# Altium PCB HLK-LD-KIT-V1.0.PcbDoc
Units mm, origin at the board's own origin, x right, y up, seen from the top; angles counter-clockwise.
Board outline 37.6 x 27.7 mm, 2 copper layers (Top Layer, Bottom Layer); 25 components, 18 nets, 85 pads, 76 vias.
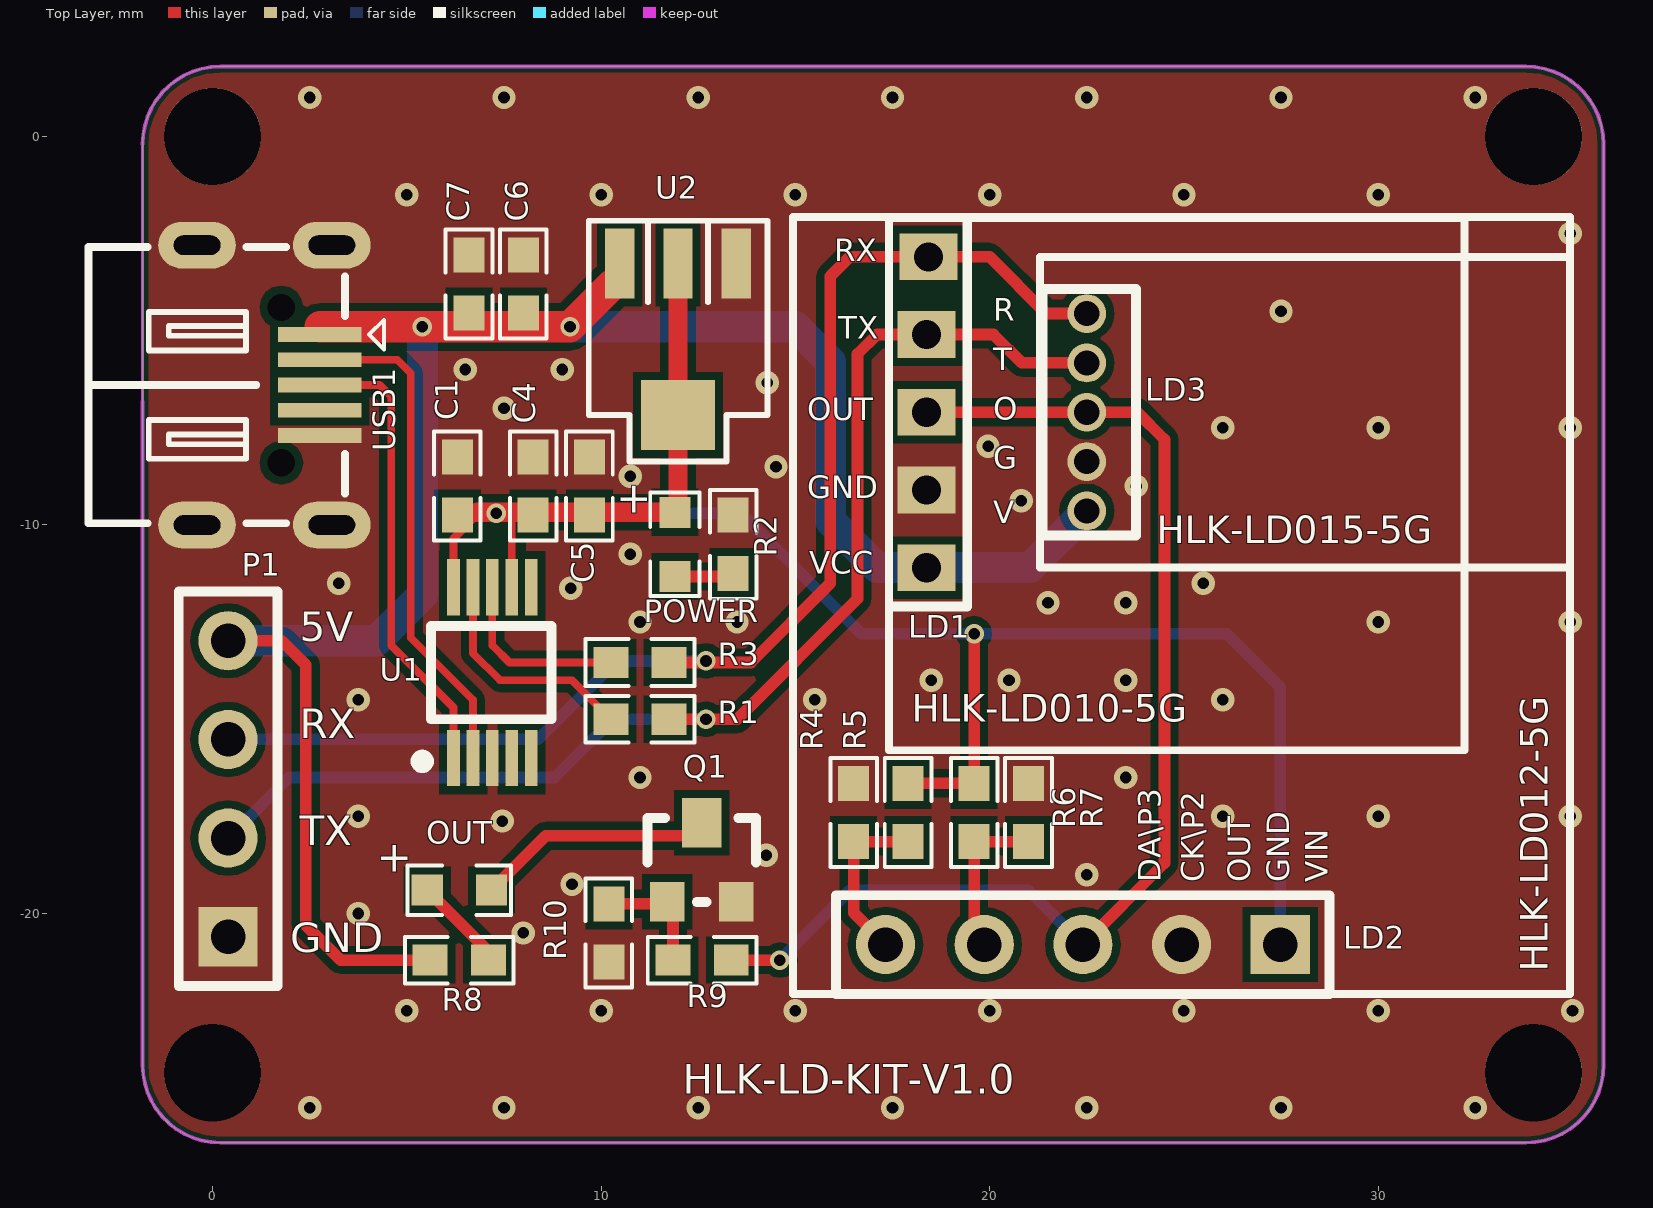
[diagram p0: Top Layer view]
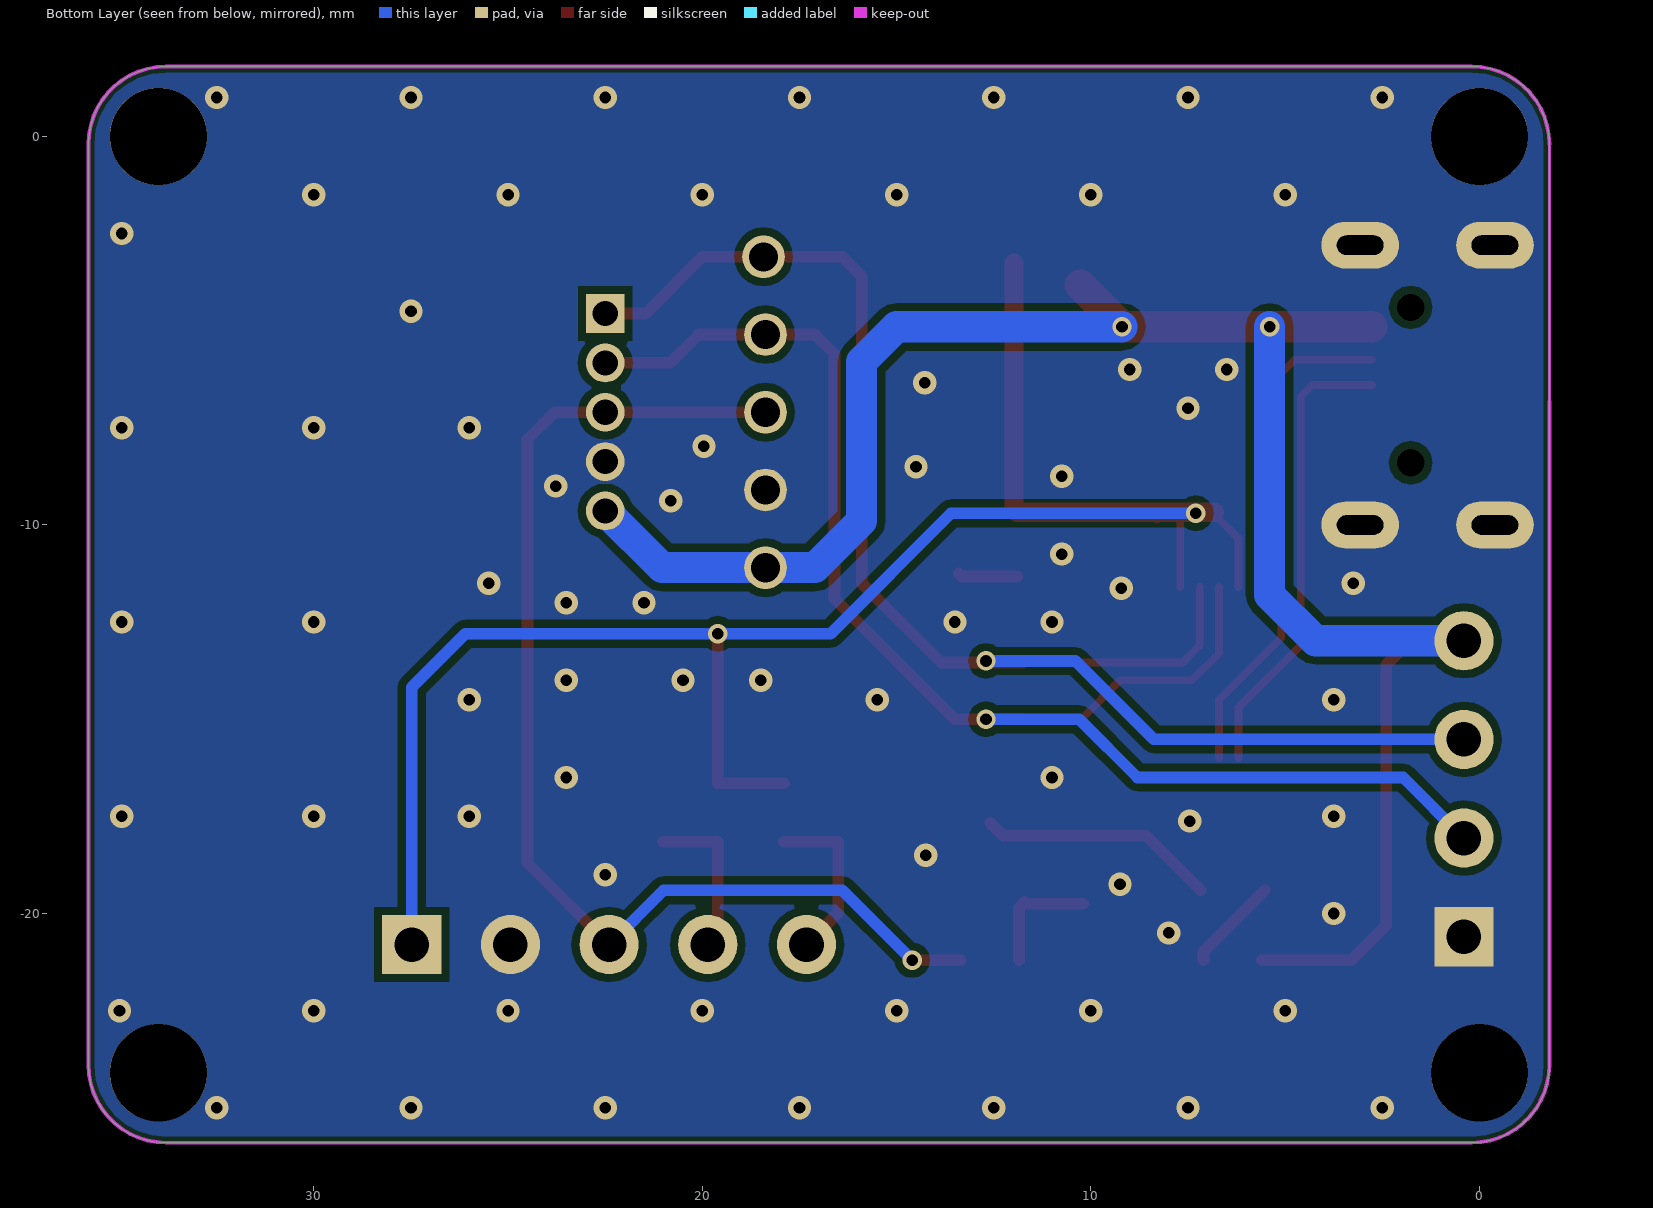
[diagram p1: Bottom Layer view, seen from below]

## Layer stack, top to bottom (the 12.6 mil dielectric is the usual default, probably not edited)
Top Layer: signal copper 0.0356
Dielectric: dielectric 0.32, FR-4, Dk 4.8
Bottom Layer: signal copper 0.0356

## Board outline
-1.8,-23.9 -1.8,-0.2 cw(c0.2,-0.2) 0.2,1.8 33.8,1.8 cw(c33.8,-0.2) 35.8,-0.2 35.8,-23.9 cw(c33.8,-23.9) 33.8,-25.9 0.2,-25.9 cw(c0.2,-23.9)

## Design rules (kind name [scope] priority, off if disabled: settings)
Clearance Clearance_1 [OnLayer('Keep-Out Layer')] p1: gap=0.1
Clearance [All] p2: gap=0.2
PolygonConnect [All] p1: connectstyle=Direct reliefconductorwidth=0.254 reliefentries=4 polygonreliefangle="90 Angle"
RoutingVias [All] p1: holewidth=0.3 width=0.5 viastyle="Through Hole" minholewidth=0.3 minwidth=0.5 maxholewidth=0.711 maxwidth=1.27
SilkscreenOverComponentPads [IsPad] p1: minsilkscreentomaskgap=0.254
SolderMaskExpansion [All] p1: expansion=0.102
TestPointUsage [All] p1: valid=0 allowmultiple=FALSE
Testpoint [(IsPad And (OnTopLayer Or OnBottomLayer))] p1: side=3 testpointundercomponent=TRUE minsize=1.016 maxsize=2.54 preferedsize=1.524 minholesize=0 maxholesize=1.016 preferedholesize=0.813 testpointgrid=0.025 style=297 order=0-112345678
Width 5V [InNet('5V')] p1: maxlimit=2 minlimit=0.3 preferedwidth=0.3
Width [All] p2: maxlimit=2 minlimit=0.2 preferedwidth=0.3
23 further rules are at their usual default settings.

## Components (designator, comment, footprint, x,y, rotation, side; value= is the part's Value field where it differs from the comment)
C1 "0.1uF" 0603 6.3,-9 r270 top
C4 "10uF" 0603 8.25,-9 r270 top
C5 "0.1uF" 0603 9.7,-9 r270 top
C6 "10uF" 0603 8,-3.8 r90 top
C7 "0.1uF" 0603 6.6,-3.8 r90 top
LD1 "HLK-LD010-5G" HLK-LD010-5G 18.4,-7.1 r0 top locked
LD2 "HLK-LD012-5G" HLK-LD012-5G 22.4,-20.8 r90 top locked
LD3 "HLK-LD015-5G" HLK-LD015-5G 22.5,-7.1 r0 top locked
OUT "" 0603LED 6.35,-19.4 r0 top (schematic designator NETLIGHT1)
P1 "2.54*4单排插针" SIP_4P_2.54 0.4,-20.6 r90 top
POWER "LED" 0603LED 11.9,-10.5 r270 top (schematic designator POWER1)
Q1 "3904" SOT-23 11.7,-19.7 r0 top
R1 "1K" 0603 11,-15 r180 top
R2 "1K" 0603 13.4,-10.5 r90 top
R3 "1K" 0603 11,-13.541 r180 top
R4 "NC/4.7K" 0603 16.5,-17.4 r90 top
R5 "NC/4.7K" 0603 17.9,-17.4 r90 top
R6 "NC/4.7K" 0603 19.6,-17.4 r90 top
R7 "NC/4.7K" 0603 21,-17.4 r90 top
R8 "1K" 0603 6.35,-21.2 r0 top
R9 "4.7K" 0603 12.6,-21.2 r0 top
R10 "47K" 0603 10.2,-20.5 r90 top
U1 "CH340E" MSOP-10 7.2,-13.8 r0 top
U2 "AMS1117" 1117 13.5,-3.2 r180 top
USB1 "micro usb" USB-MICRO_D -0.4,-6.4 r270 top

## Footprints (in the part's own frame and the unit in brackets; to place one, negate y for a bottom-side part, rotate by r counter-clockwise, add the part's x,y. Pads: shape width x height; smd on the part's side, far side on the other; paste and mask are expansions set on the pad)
0603 [mm]
  rect 0.9x0.8 smd: 1(-0.75,0) 2(0.75,0)
  silkscreen extent -1.4,-0.6 1.4,0.6
0603LED [mm]
  rect 0.8x0.8 smd: 1(-0.826,0) 2(0.826,0)
  silkscreen extent -1.33,-0.64 1.33,0.64
1117 [mm]
  rect 1.9x1.8 smd: 0(1.52,3.97)
  rect 0.75x1.8 smd: 1(0.02,0.07) 2(1.52,0.07) 3(3.02,0.07)
  silkscreen extent -0.78,-1.03 3.82,5.17, body extent -0.73,0.14 3.77,4.14, height 1.5
HLK-LD010-5G [mm]
  rect 1.5x1.2 / inner rrect0% 1.2x1.2 / far side round 1.1 hole 0.75: 1(0.025,4) 2(-0.025,2) 3(-0.025,0) 4(-0.025,-2) 5(-0.025,-4)
  silkscreen extent -0.99,-8.7 13.83,5
HLK-LD012-5G [mil]
  round 60 hole 35: 1(0,200) 2(0,100) 3(0,0) 4(0,-100)
  rect 60x60 / inner round 60 / far side rect 60x60 hole 35: 5(0,-200)
  silkscreen extent -50,-494 737,294
HLK-LD015-5G [mm]
  round 1 / inner round 1 / far side rect 1x1 hole 0.65: 1(0,2.54)
  round 1 hole 0.65: 2(0,1.27) 3(0,0) 4(0,-1.27) 5(0,-2.54)
  silkscreen extent -1.2,-4 12.4,4
MSOP-10 [mm]
  rect 0.33x1.45 smd: 1(-1,-2.2) 2(-0.5,-2.2) 3(0,-2.2) 4(0.5,-2.2) 5(1,-2.2) 6(1,2.2) 7(0.5,2.2) 8(0,2.2) 9(-0.5,2.2) 10(-1,2.2)
  silkscreen extent -1.95,-2.44 1.53,1.2
SIP_4P_2.54 [mil]
  rect 60x60 / inner round 60 / far side rect 60x60 hole 35: 1(0,0)
  round 60 hole 35: 2(100,0) 3(200,0) 4(300,0)
  silkscreen extent -50,-50 350,50
SOT-23 [mil]
  rect 35x40 smd: 1(0,0) 2(70,0)
  rect 40x50 smd: 3(35,80)
  silkscreen extent -20,0 90,85
USB-MICRO_D [mm] "micro型USB ，6.7*7.5*2.5mm"
  round 0 hole 0.7 unplated: 0(-2,2.17) 0(2,2.17)
  rect 0.381x2.15 smd: 1(-1.3,3.16) 2(-0.65,3.16) 3(0,3.16) 4(0.65,3.16) 5(1.3,3.16)
  oval 1.2x2 hole 0.5 slot 1.2 at 90 deg: 6(3.6,3.47) 7(3.6,0) 8(-3.6,0) 9(-3.6,3.47)
  silkscreen extent -3.56,-2.79 3.56,4.81

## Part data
C1: library part CAP, "Capacitor"
C4 C5 C6 C7: library part Cap, "Capacitor"
OUT: library part LED
P1: library part 2.54*2插针
Q1: library part A09T, "NPN General Purpose Amplifier"
R1 R2 R3 R4 R5 R6 R7 R8 R9 R10: library part Res1, "Resistor"
U2: library part Component_1
USB1: library part USB-D

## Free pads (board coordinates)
  round 2.5 hole 2.5: 0(0,-24.1) 0(34,0) 2(0,0) 2(34,-24.1)

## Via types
v1: diameter 0.6, hole 0.3, Top Layer to Bottom Layer, tented both sides, 69 vias
v2: diameter 0.5, hole 0.3, Top Layer to Bottom Layer, tented both sides, 7 vias

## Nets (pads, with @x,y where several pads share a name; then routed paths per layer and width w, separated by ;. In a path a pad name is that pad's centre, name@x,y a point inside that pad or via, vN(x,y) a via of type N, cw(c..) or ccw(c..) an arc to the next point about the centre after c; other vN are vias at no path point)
5V: C6.1 C7.1 LD1.5 LD3.5 P1.4 R8.1 U2.3 USB1.1 | length 51.8
  Top Layer w0.3: P1.4 1.78,-12.98 2.4,-13.6 2.4,-20.3 3.3,-21.2 R8.1
  Top Layer w0.8: 2.76,-4.9 v2(5.4,-4.9) v2(9.2,-4.9) U2.3@10.275,-3.825
  Bottom Layer w0.8: P1.4 4.22,-12.98 5.4,-11.8 v2(5.4,-4.9) ; v2(9.2,-4.9) 15,-4.9 15.9,-5.8 15.9,-9.9 17.1,-11.1 LD1.5 21.04,-11.1 LD3.5
CTS: U1.5
DM: U1.2 USB1.2 | length 13
  Top Layer w0.2: USB1.2 4.75,-5.75 5.1,-6.1 5.1,-12.9 6.7,-14.5 U1.2
DP: U1.1 USB1.3 | length 11.9
  Top Layer w0.203: USB1.3 4.3,-6.4 4.6,-6.7 4.6,-13.1 6.2,-14.7 U1.1
GND: C1.1 C4.1 C5.1 C6.2 C7.2 LD1.4 LD2.4 LD3.4 P1.1 pad.0 pad.2 Q1.2 R2.2 R4.2 R7.2 R10.1 U1.3 U2.1 USB1.5 USB1.6 USB1.7 USB1.8 USB1.9
  other v1: 2.5,-25 7.5,-25 12.5,-25 17.5,-25 22.5,-25 27.5,-25 32.5,-25 5,-22.5 10,-22.5 15,-22.5 20,-22.5 25,-22.5 30,-22.5 35,-22.5 8,-20.5 3.75,-20 9.25,-19.25 22.5,-19 14.25,-18.5 7.452,-17.622 3.75,-17.5 26,-17.5 30,-17.5 34.94,-17.5 11,-16.5 23.5,-16.5 3.75,-14.5 15.5,-14.5 26,-14.5 18.5,-14 20.5,-14 23.5,-14 11,-12.5 13.5,-12.5 30,-12.5 34.94,-12.5 21.5,-12 23.5,-12 9.222,-11.627 3.25,-11.5 25.5,-11.5 10.75,-10.75 20.81,-9.381 23.77,-9 10.75,-8.75 14.5,-8.5 19.96,-7.972 26,-7.5 30,-7.5 34.94,-7.5 7.5,-7 14.28,-6.341 6.5,-6 9,-6 27.5,-4.5 34.94,-2.5 5,-1.5 10,-1.5 15,-1.5 20,-1.5 25,-1.5 30,-1.5 2.5,1 7.5,1 12.5,1 17.5,1 22.5,1 27.5,1 32.5,1
NetLD2_1: LD2.1 R4.1 R5.1 | length 4.4
  Top Layer w0.3: LD2.1 16.5,-19.98 R4.1 R5.1
NetLD2_2: LD2.2 R6.1 R7.1 | length 4.2
  Top Layer w0.3: LD2.2 19.6,-20.54 R6.1 R7.1
NetOUT_1: OUT.1 R8.2 | length 2.5
  Top Layer w0.3: OUT.1 7.1,-20.976 R8.2
NetOUT_2: OUT.2 Q1.3 | length 6.1
  Top Layer w0.3: OUT.2 8.575,-18 12.257,-18 Q1.3
NetPOWER_2: POWER.2 R2.1 | length 1.5
  Top Layer w0.3: POWER.2 13.324,-11.325 R2.1
NetQ1_1: Q1.1 R9.1 R10.2 | length 3.1
  Top Layer w0.3: R10.2 11.65,-19.75 Q1.1 11.85,-19.85 R9.1
OUT: LD1.3 LD2.3 LD3.3 R9.2 | length 30.7
  Top Layer w0.3: R9.2 v2(14.6,-21.2) ; LD1.3 LD3.3 23.8,-7.1 24.5,-7.8 24.5,-18.7 LD2.3
  Bottom Layer w0.3: v2(14.6,-21.2) 16.4,-19.4 21,-19.4 LD2.3
RTS: U1.4
RX: LD1.1 LD3.1 P1.3 R3.1 | length 33.4
  Top Layer w0.3: R3.1 13.859,-13.541 15.9,-11.5 15.9,-3.6 16.4,-3.1 LD1.1 20,-3.1 21.46,-4.56 LD3.1
  Bottom Layer w0.3: P1.3 8.38,-15.52 10.4,-13.5 v2(12.7,-13.5)
RX0_CH340: R1.2 U1.9 | length 6
  Top Layer w0.2: U1.9 6.7,-13.3 7.4,-14 9.25,-14 R1.2
TX: LD1.2 LD3.2 P1.2 R1.1 | length 32.4
  Top Layer w0.3: R1.1 v2(12.7,-15) 13.5,-15 16.6,-11.9 16.6,-5.6 17.1,-5.1 LD1.2 20.1,-5.1 20.83,-5.83 LD3.2
  Bottom Layer w0.3: P1.2 1.96,-16.5 8.8,-16.5 10.3,-15 v2(12.7,-15)
TX0_CH340: R3.2 U1.8 | length 4.7
  Top Layer w0.2: U1.8 7.2,-13.1 7.641,-13.541 R3.2
V3.3: C1.2 C4.2 C5.2 LD2.5 POWER.1 R5.2 R6.2 U1.7 U1.10 U2.0 U2.2 | length 50.3
  Top Layer w0.2: U1.10 6.2,-10.35 6.8,-9.75 ; U1.7 7.7,-9.8
  Top Layer w0.3: 6.8,-9.7 6.825,-9.674 ; C4.2 C4.2@8.3,-9.8 ; R5.2 R6.2 v2(19.6,-12.8)
  Top Layer w0.5: 6.825,-9.674 8.25,-9.674 C5.2@9.7,-9.674 ; 9.1,-9.674 POWER.1 11.98,-9.595 11.98,-8.7 U2.0 U2.2
  Bottom Layer w0.3: v2(7.3,-9.7) 13.6,-9.7 16.7,-12.8 v2(19.6,-12.8) 26.1,-12.8 27.48,-14.18 LD2.5
pads on no net: U1.6 USB1.0 USB1.4

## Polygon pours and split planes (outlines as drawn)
GND on Top Layer "Keep-Out Layer-No Net" (solid, remove dead copper, pour order 1000): -2.1,2.2 -2.1,-26 -2.1,-26.6 36.8,-26.6 36.8,2 36.7,2.1 -2,2.1 -2.1,2.2
GND on Bottom Layer "Keep-Out Layer-No Net" (solid, remove dead copper, pour order 1001): -2.1,2.2 -2.1,-26 -2.1,-26.6 36.8,-26.6 36.8,2 36.7,2.1 -2,2.1 -2.1,2.2

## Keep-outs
Keep-Out Layer:
  lines w0.08: -1.8,-6.826 -1.8,-0.2
  lines w0.1: -1.8,-6.826 -1.8,-23.9 ccw(c0.2,-23.9) 0.2,-25.9 33.8,-25.9 ccw(c33.8,-23.9) 35.8,-23.9 35.8,-0.2 ccw(c33.8,-0.2) 33.8,1.8 0.2,1.8 ccw(c0.2,-0.2) -1.8,-0.2

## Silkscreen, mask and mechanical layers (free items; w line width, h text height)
Top Overlay:
  text "5V" at 2.25,-13.25 h1.3
  text "RX" at 2.25,-15.75 h1.3
  text "TX" at 2.25,-18.5 h1.3
  text "GND" at 2,-21.25 h1.3
  text "HLK-LD-KIT-V1.0" at 12.1,-24.9 h1.3
Top Solder:
  rectangle: 5.9,-12.5 8.5,-10.7
  rectangle: 5.9,-16.9 8.5,-15.1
